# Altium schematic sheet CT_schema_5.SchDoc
size 300 x 247 mm
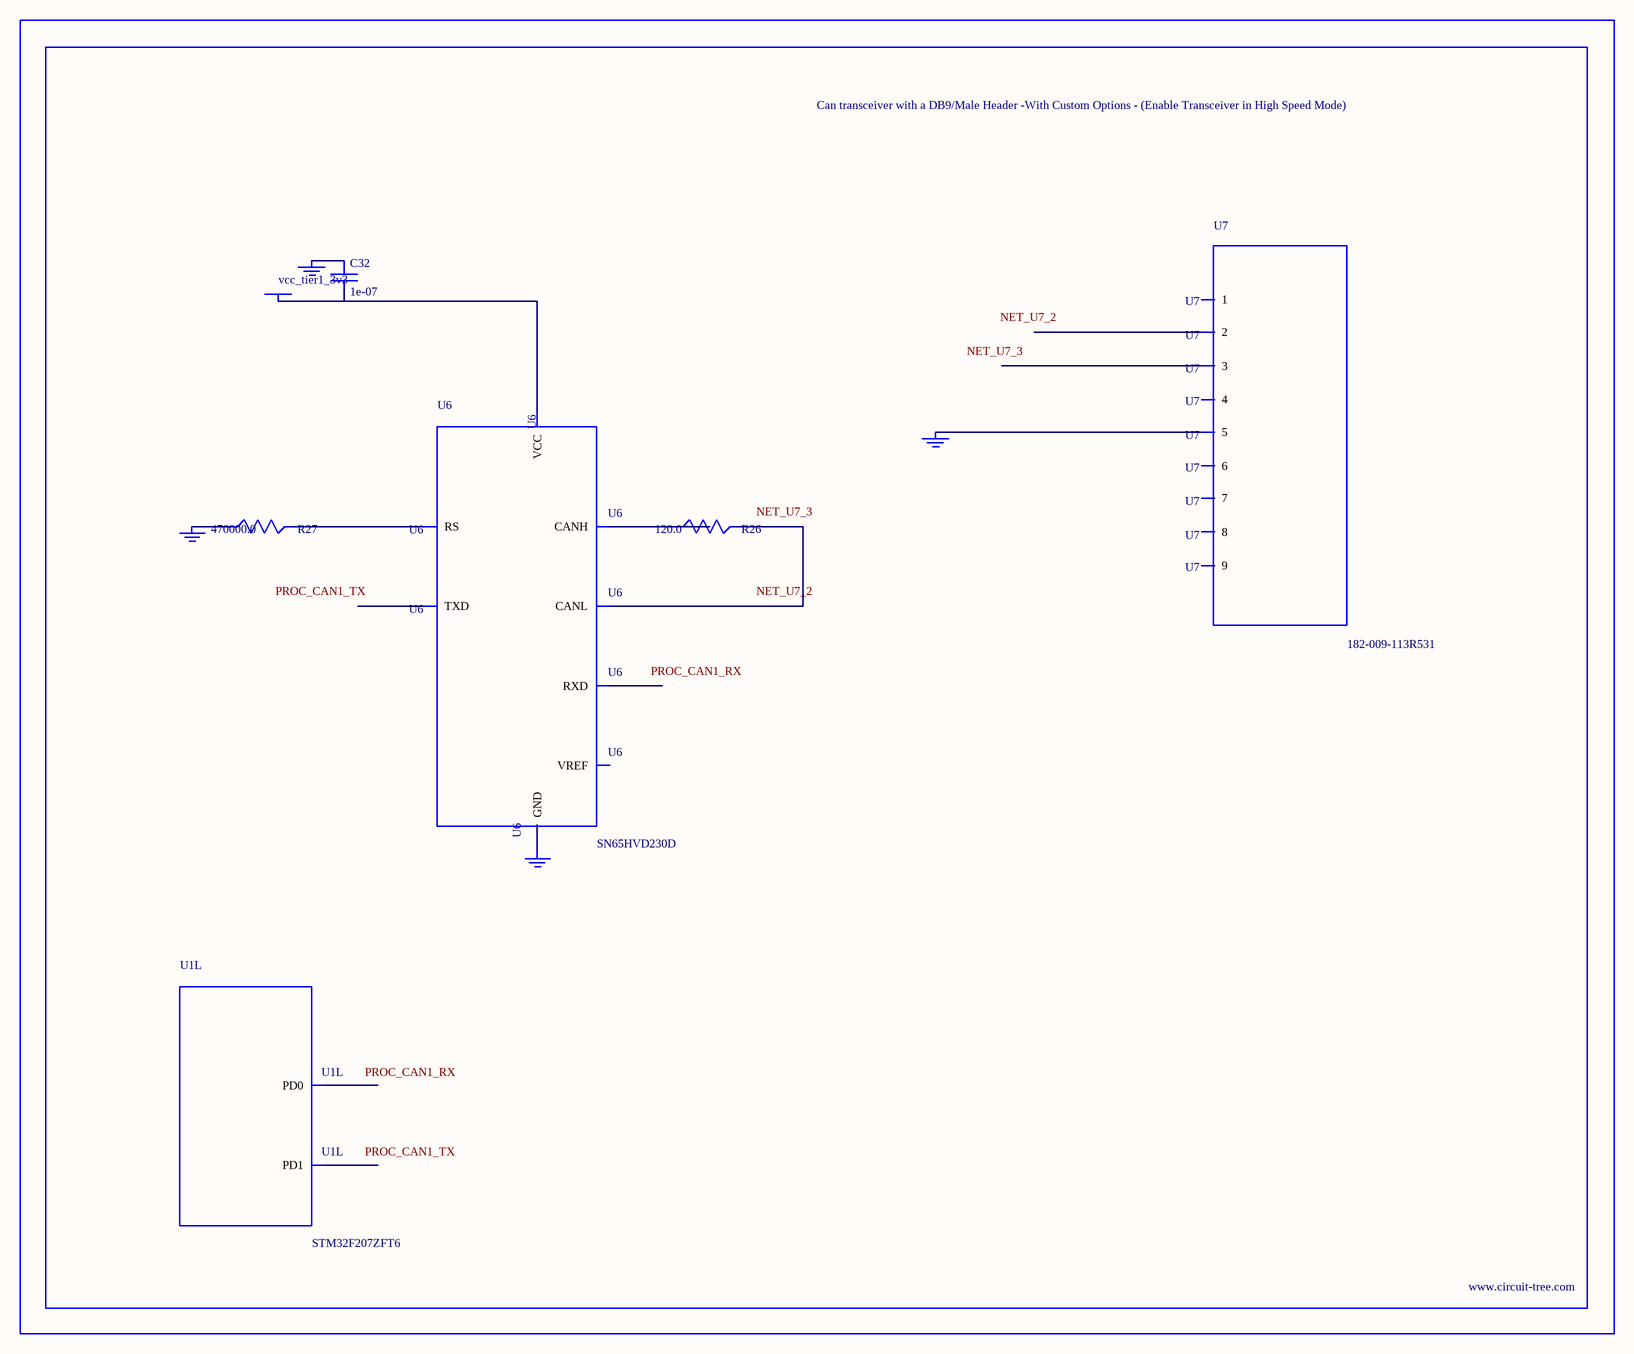
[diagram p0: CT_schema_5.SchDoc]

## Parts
BORDER4  (no value)
C32  1e-07  [C0402]
GND_INSTANCE_4_0  (no value)
GND_INSTANCE_4_1  (no value)
GND_INSTANCE_4_2  (no value)
GND_INSTANCE_4_3  (no value)
POWER_INSTANCE_4_0  vcc_tier1_3v3
R26  120.0  [R0603]
R27  470000.0  [R0603]
U1  STM32F207ZFT6  [LQFP144]  (part L of 13)
U6  SN65HVD230D  [SOIC-8]
U7  182-009-113R531  [182-009-MALE]

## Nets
NetC32_1: C32.1 GND_INSTANCE_4_0.0(GND)
NetC32_2: C32.2 POWER_INSTANCE_4_0.0(PWR) U6.3(VCC)
NetGND_INSTANCE_4_1_0: GND_INSTANCE_4_1.0(GND) R27.1
NetGND_INSTANCE_4_2_0: GND_INSTANCE_4_2.0(GND) U6.2(GND)
NetGND_INSTANCE_4_3_0: GND_INSTANCE_4_3.0(GND) U7.5
NetR26_1: R26.1 U6.7(CANH)
NetR26_2: R26.2 U6.6(CANL)
NetR27_2: R27.2 U6.8(RS)

Not connected (* = marked no-connect by the designer): U1 114(PD0) 115(PD1); U6 1(TXD) 4(RXD) 5(VREF); U7 1 2 3 4 6 7 8 9

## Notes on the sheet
- Labels drawn without touching a wire or pin: NET_U7_2, NET_U7_3, PROC_CAN1_RX, PROC_CAN1_TX

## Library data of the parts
BORDER4 = BORDER_PAGE4
C32 = C0402C104K3RACTU
GND_INSTANCE_4_0-GND_INSTANCE_4_3 = GND
POWER_INSTANCE_4_0 = PWR
R26 = RC0603JR-07120RL
R27 = RC0603JR-07470KL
